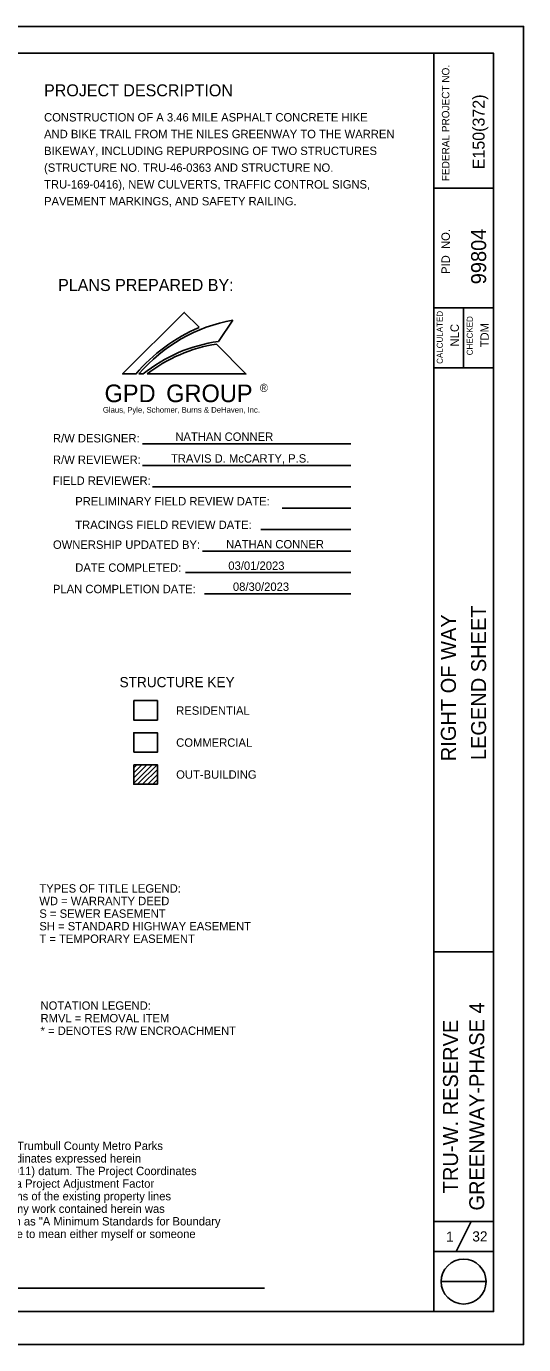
# Model space of a CAD drawing. Extents: x 0 to 34, y -0.1 to 32.4.
# Drawn here: x 25.7 to 34, y -0.05 to 21.95 of the extents above; entities that cross this region are included whole.
import ezdxf

# ---------------------------------------------------------------- set-up
doc = ezdxf.new("R2010")
doc.units = 0
for name, color, linetype in [('Default', 7, 'Continuous'), ('GM_X_Section', 7, 'Continuous'), ('GM_X_Township', 7, 'Continuous'), ('SH_Border', 7, 'Continuous'), ('SH_Cut_Line', 7, 'Continuous'), ('SH_Data', 7, 'Continuous'), ('TX_P_Misc', 7, 'Continuous')]:
    doc.layers.add(name, color=color, linetype=linetype)

msp = doc.modelspace()

# ---------------------------------------------------------------- linework, layer by layer
at = {"layer": 'GM_X_Section'}
for points in [[(28.588, 16.925), (28.338, 17.175), (27.309, 16.146), (27.529, 16.146)], [(28.909, 16.69), (29.152, 17.046)], [(27.719, 16.146), (29.367, 16.146), (28.875, 16.645)], [(27.583, 16.146), (27.652, 16.146)]]:
    msp.add_lwpolyline(points, dxfattribs=at)
for centre, radius, start, end in [((29.631, 14.394), 2.695, 100.243, 139.4433), ((29.728, 14.268), 2.891, 113.2298, 139.5003), ((29.273, 14.126), 2.59, 98.0938, 128.7478), ((29.274, 14.134), 2.543, 99.0316, 127.6933)]:
    msp.add_arc(centre, radius, start, end, dxfattribs=at)
at = {"layer": 'GM_X_Township'}
msp.add_lwpolyline([(27.495, 9.834), (27.892, 9.834), (27.892, 10.16), (27.495, 10.16)], close=True, dxfattribs=at)
at = {"layer": 'SH_Border'}
msp.add_lwpolyline([(0.001, -0.053), (34.001, -0.053), (34.001, 21.947), (0.001, 21.947)], close=True, dxfattribs=at)
at = {"layer": 'SH_Cut_Line'}
msp.add_line((32.625, 1), (33.375, 1), dxfattribs=at)
msp.add_circle((33, 1), 0.375, dxfattribs=at)
at = {"layer": 'SH_Data'}
for p, q in [((32.5, 0.5), (32.5, 21.5)), ((32.5, 19.25), (33.5, 19.25)), ((32.5, 17.25), (33.5, 17.25)), ((32.5, 17.25), (33.5, 17.25)), ((33, 17.25), (33, 16.25)), ((32.5, 16.25), (33.5, 16.25)), ((32.5, 6.5), (33.5, 6.5)), ((32.5, 2), (33.5, 2)), ((33.125, 2), (32.875, 1.5)), ((32.5, 1.5), (33.5, 1.5))]:
    msp.add_line(p, q, dxfattribs=at)
msp.add_lwpolyline([(2, 21.5), (33.5, 21.5), (33.5, 0.5), (2, 0.5)], close=True, dxfattribs=at)
at = {"layer": 'TX_P_Misc'}
for p, q in [((27.644, 14.978), (31.117, 14.978)), ((27.644, 14.621), (31.117, 14.621)), ((27.808, 14.264), (31.117, 14.264)), ((29.971, 13.906), (31.117, 13.906)), ((29.614, 13.549), (31.117, 13.549)), ((28.644, 13.192), (31.117, 13.192)), ((28.359, 12.835), (31.117, 12.835)), ((28.674, 12.478), (31.117, 12.478)), ((27.495, 9.624), (27.497, 9.625)), ((27.495, 9.574), (27.547, 9.625)), ((27.495, 9.489), (27.631, 9.625)), ((27.495, 9.404), (27.716, 9.625)), ((27.495, 9.319), (27.801, 9.625)), ((27.56, 9.299), (27.886, 9.625)), ((27.644, 9.299), (27.892, 9.547)), ((27.729, 9.299), (27.892, 9.462)), ((27.495, 9.304), (27.5, 9.299)), ((27.814, 9.299), (27.892, 9.378)), ((18.737, 0.89), (29.675, 0.89))]:
    msp.add_line(p, q, dxfattribs=at)
for points in [[(27.495, 10.696), (27.892, 10.696), (27.892, 10.37), (27.495, 10.37)], [(27.495, 9.625), (27.892, 9.625), (27.892, 9.299), (27.495, 9.299)]]:
    msp.add_lwpolyline(points, close=True, dxfattribs=at)

# ---------------------------------------------------------------- texts
at = {"layer": 'Default'}
for s, height, p in [('GPD', 0.294, (27.009, 15.676)), ('GROUP', 0.294, (28.037, 15.676)), ('®', 0.137, (29.601, 15.846)), ('Glaus, Pyle, Schomer, Burns & DeHaven, Inc.', 0.09609, (26.981, 15.5))]:
    msp.add_text(s, height=height, dxfattribs=at).set_placement(p)
at = {"layer": 'GM_X_Section'}
for s, p in [('NATHAN CONNER', (28.19, 15.03)), ('TRAVIS D. McCARTY, P.S.', (28.117, 14.667)), ('NATHAN CONNER', (29.037, 13.235)), ('03/01/2023', (29.074, 12.877)), ('08/30/2023', (29.151, 12.526))]:
    msp.add_text(s, height=0.14, dxfattribs=at).set_placement(p)
at = {"layer": 'SH_Cut_Line'}
for s, height, p in [('FEDERAL PROJECT NO.', 0.125, (32.762, 19.364)), ('E150(372)', 0.2, (33.35, 19.562)), ('PID  NO.', 0.14, (32.77, 17.816)), ('99804', 0.25, (33.375, 17.643)), ('CALCULATED', 0.1, (32.652, 16.315)), ('NLC', 0.14, (32.92, 16.606)), ('CHECKED', 0.1, (33.152, 16.458)), ('TDM', 0.14, (33.42, 16.591)), ('RIGHT OF WAY', 0.25, (32.871, 9.684)), ('LEGEND SHEET', 0.25, (33.375, 9.702)), ('GREENWAY-PHASE 4', 0.25, (33.344, 2.185)), ('TRU-W. RESERVE', 0.25, (32.906, 2.473))]:
    msp.add_text(s, height=height, rotation=90, dxfattribs=at).set_placement(p)
for s, height, p in [('PROJECT DESCRIPTION', 0.2, (26, 20.78)), ('CONSTRUCTION OF A 3.46 MILE ASPHALT CONCRETE HIKE ', 0.14, (26, 20.36)), ('AND BIKE TRAIL FROM THE NILES GREENWAY TO THE WARREN', 0.14, (26, 20.081)), ('BIKEWAY, INCLUDING REPURPOSING OF TWO STRUCTURES', 0.14, (26, 19.8)), ('(STRUCTURE NO. TRU-46-0363 AND STRUCTURE NO. ', 0.14, (26, 19.52)), ('TRU-169-0416), NEW CULVERTS, TRAFFIC CONTROL SIGNS, ', 0.14, (26, 19.241)), ('PAVEMENT MARKINGS, AND SAFETY RAILING.', 0.14, (26, 18.96)), ('1', 0.17, (32.707, 1.665)), ('32', 0.17, (33.145, 1.669))]:
    msp.add_text(s, height=height, dxfattribs=at).set_placement(p)
at = {"layer": 'TX_P_Misc'}
for s, height, p in [('PLANS PREPARED BY:', 0.2, (26.234, 17.531)), ('R/W DESIGNER:', 0.14, (26.148, 15.004)), ('R/W REVIEWER:', 0.14, (26.148, 14.645)), ('FIELD REVIEWER:', 0.14, (26.147, 14.296)), ('PRELIMINARY FIELD REVIEW DATE:', 0.14, (26.52, 13.952)), ('TRACINGS FIELD REVIEW DATE:', 0.14, (26.52, 13.559)), ('OWNERSHIP UPDATED BY:', 0.14, (26.148, 13.228)), ('DATE COMPLETED:', 0.14, (26.52, 12.845)), ('PLAN COMPLETION DATE:', 0.14, (26.148, 12.488)), ('STRUCTURE KEY', 0.17, (27.259, 10.919)), ('RESIDENTIAL', 0.14, (28.204, 10.459)), ('COMMERCIAL', 0.14, (28.204, 9.925)), ('OUT-BUILDING', 0.14, (28.204, 9.392)), ('TYPES OF TITLE LEGEND:', 0.14, (25.921, 7.491)), ('WD = WARRANTY DEED', 0.14, (25.921, 7.281)), ('S = SEWER EASEMENT', 0.14, (25.921, 7.071)), ('SH = STANDARD HIGHWAY EASEMENT', 0.14, (25.921, 6.861)), ('T = TEMPORARY EASEMENT', 0.14, (25.921, 6.651)), ('NOTATION LEGEND:', 0.14, (25.941, 5.536)), ('RMVL = REMOVAL ITEM', 0.14, (25.941, 5.326)), ('* = DENOTES R/W ENCROACHMENT', 0.14, (25.941, 5.116)), ('I, Steven L. Mullaney, P. S. have conducted a survey of the existing conditions for Trumbull County Metro Parks', 0.14, (18.732, 3.196)), ('in May 2017.  The results of that survey are contained herein.  The horizontal coordinates expressed herein', 0.14, (18.732, 2.986)), ('are based on the Ohio State Plane Coordinate System, North Zone on NAD 83 (2011) datum. The Project Coordinates', 0.14, (18.732, 2.776)), ('(US Survey feet) are relative to State Plane Grid Coordinates (US Survey feet) by a Project Adjustment Factor', 0.14, (18.732, 2.566)), ('multiplier of 0.999903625.  As a part of this project I have reestablished the locations of the existing property lines', 0.14, (18.732, 2.356)), ('and centerline of existing Right of Way for property takes contained herein.  All of my work contained herein was', 0.14, (18.732, 2.146)), ('conducted in accordance with Ohio Administrative Code 4733-37 commonly known as "A Minimum Standards for Boundary', 0.14, (18.732, 1.936)), ('Surveys in the State of Ohio" unless noted.  The words I and my as used herein are to mean either myself or someone', 0.14, (18.732, 1.726))]:
    msp.add_text(s, height=height, dxfattribs=at).set_placement(p)

doc.saveas('drawing.dxf')
